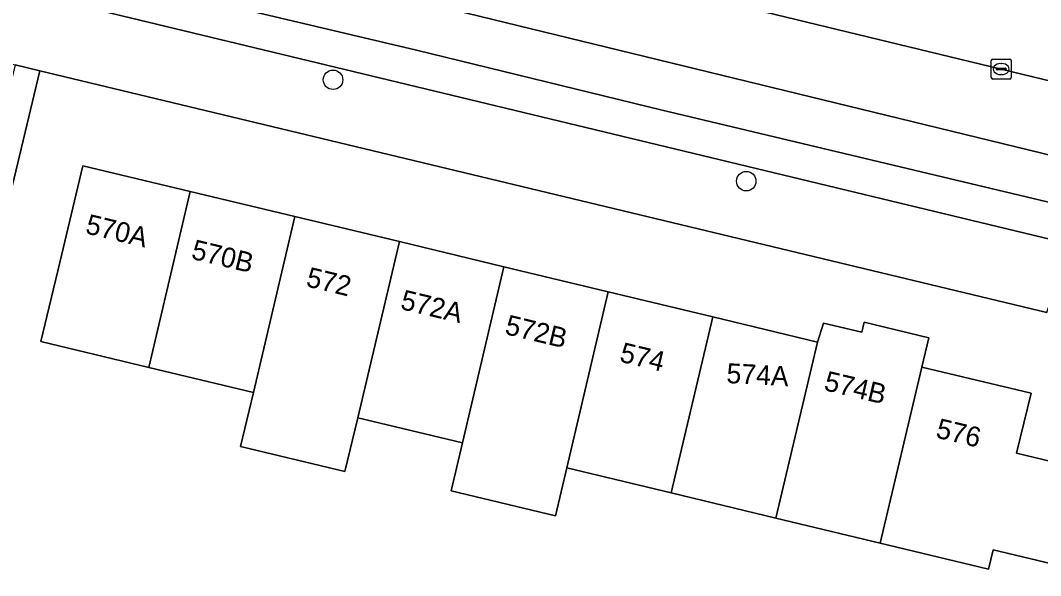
# Model space of a CAD drawing. Extents: x 157767 to 159172, y 387839 to 389425.
# Drawn here: x 158640.4 to 158691.6, y 388114.7 to 388142.5 of the extents above; entities that cross this region are included whole.
import ezdxf

# ---------------------------------------------------------------- set-up
doc = ezdxf.new("R2010")
doc.units = 0
for name, color, linetype in [('IMGEO_Berm_groen', 7, 'Continuous'), ('IMGEO_Boom', 7, 'Continuous'), ('IMGEO_Erf', 7, 'Continuous'), ('IMGEO_Kolk', 7, 'Continuous'), ('IMGEO_Pand', 7, 'Continuous'), ('IMGEO_Pand_nummerreeks', 7, 'Continuous'), ('IMGEO_Parkeervlak_open', 7, 'Continuous'), ('IMGEO_Rijbaan_lokaal_gesloten', 7, 'Continuous'), ('IMGEO_Voetpad_open', 7, 'Continuous')]:
    doc.layers.add(name, color=color, linetype=linetype)

msp = doc.modelspace()

# ---------------------------------------------------------------- linework, layer by layer
at = {"layer": 'IMGEO_Berm_groen'}
msp.add_lwpolyline([(158645.432, 388150.672), (158665.345, 388145.992), (158678.854, 388142.706), (158696.862, 388138.362), (158697.567, 388138.192), (158699.866, 388138.031)], dxfattribs=at)
at = {"layer": 'IMGEO_Boom'}
for centre in [(158656.082, 388139.564), (158676.844, 388134.473)]:
    msp.add_circle(centre, 0.489, dxfattribs=at)
at = {"layer": 'IMGEO_Erf'}
for points in [[(158691.944, 388127.877), (158641.347, 388140.021), (158634.406, 388111.104)], [(158692.191, 388115.259), (158689.254, 388115.963), (158689.02, 388114.99), (158683.578, 388116.296), (158678.326, 388117.556), (158673.076, 388118.816), (158667.824, 388120.077), (158667.254, 388117.661), (158662.014, 388118.918), (158662.583, 388121.335), (158657.331, 388122.595), (158656.681, 388119.885), (158651.429, 388121.145), (158652.079, 388123.855), (158646.829, 388125.115), (158641.397, 388126.419), (158642.35, 388130.39), (158643.517, 388135.251), (158648.905, 388133.958), (158654.157, 388132.697), (158659.412, 388131.436), (158664.663, 388130.176), (158669.91, 388128.917), (158675.167, 388127.655), (158680.418, 388126.395), (158680.729, 388127.349), (158682.645, 388126.893), (158682.763, 388127.388), (158686.016, 388126.605), (158685.668, 388125.135), (158691.151, 388123.819), (158690.43, 388120.815), (158693.356, 388120.112)]]:
    msp.add_lwpolyline(points, dxfattribs=at)
at = {"layer": 'IMGEO_Kolk'}
for p, q in [((158689.155, 388139.676), (158689.155, 388140.528)), ((158689.23, 388140.602), (158690.082, 388140.602)), ((158689.414, 388140.096), (158689.414, 388140.108)), ((158689.457, 388140.145), (158689.855, 388140.145)), ((158689.643, 388140.382), (158689.668, 388140.382)), ((158689.898, 388140.108), (158689.898, 388140.096)), ((158690.156, 388140.528), (158690.156, 388139.676)), ((158690.082, 388139.602), (158689.23, 388139.602)), ((158689.852, 388140.059), (158689.454, 388140.059)), ((158689.666, 388139.822), (158689.641, 388139.822))]:
    msp.add_line(p, q, dxfattribs=at)
for points in [[(158689.155, 388139.676), (158689.155, 388140.528)], [(158689.23, 388140.602), (158690.082, 388140.602)], [(158690.156, 388140.528), (158690.156, 388139.676)], [(158690.082, 388139.602), (158689.23, 388139.602)]]:
    msp.add_lwpolyline(points, dxfattribs=at)
for centre, radius, start, end in [((158689.232, 388140.526), 0.0765, 91.552, 178.448), ((158689.232, 388140.526), 0.0765, 91.552, 178.448), ((158689.454, 388140.105), 0.0403, 85.8775, 175.7526), ((158689.451, 388140.095), 0.0366, 178.938, 274.7102), ((158689.855, 388140.102), 0.043, 264.8664, 352.4533), ((158689.859, 388140.107), 0.0386, 1.7309, 96.639), ((158690.08, 388140.526), 0.0765, 1.552, 88.448), ((158690.08, 388140.526), 0.0765, 1.552, 88.448), ((158689.232, 388139.678), 0.0765, 181.552, 268.448), ((158689.232, 388139.678), 0.0765, 181.552, 268.448), ((158690.08, 388139.678), 0.0765, 271.552, 358.448), ((158690.08, 388139.678), 0.0765, 271.552, 358.448)]:
    msp.add_arc(centre, radius, start, end, dxfattribs=at)
for centre, major_axis, ratio, start_param, end_param in [((158689.642, 388140.102), (-0.387, 0.002), 0.722429, 4.712389, 7.853982), ((158689.667, 388140.102), (-0.39, 0.002), 0.717154, 1.570796, 4.712389)]:
    msp.add_ellipse(centre, major_axis=major_axis, ratio=ratio, start_param=start_param, end_param=end_param, dxfattribs=at)
at = {"layer": 'IMGEO_Pand'}
for points in [[(158646.829, 388125.115), (158648.905, 388133.958), (158643.517, 388135.251), (158642.35, 388130.39), (158641.397, 388126.419)], [(158654.157, 388132.697), (158648.905, 388133.958), (158646.829, 388125.115), (158652.079, 388123.855)], [(158654.157, 388132.697), (158652.079, 388123.855), (158651.429, 388121.145), (158656.681, 388119.885), (158657.331, 388122.595), (158659.412, 388131.436)], [(158664.663, 388130.176), (158659.412, 388131.436), (158657.331, 388122.595), (158662.583, 388121.335)], [(158669.91, 388128.917), (158664.663, 388130.176), (158662.583, 388121.335), (158662.014, 388118.918), (158667.254, 388117.661), (158667.824, 388120.077)], [(158669.91, 388128.917), (158667.824, 388120.077), (158673.076, 388118.816), (158675.167, 388127.655)], [(158678.326, 388117.556), (158680.418, 388126.395), (158675.167, 388127.655), (158673.076, 388118.816)], [(158685.668, 388125.135), (158686.016, 388126.605), (158682.763, 388127.388), (158682.645, 388126.893), (158680.729, 388127.349), (158680.418, 388126.395), (158678.326, 388117.556), (158683.578, 388116.296)], [(158691.151, 388123.819), (158685.668, 388125.135), (158683.578, 388116.296), (158689.02, 388114.99), (158689.254, 388115.963), (158692.191, 388115.259), (158693.356, 388120.112), (158690.43, 388120.815)]]:
    msp.add_lwpolyline(points, close=True, dxfattribs=at)
at = {"layer": 'IMGEO_Parkeervlak_open'}
for points in [[(158696.145, 388132.346), (158694.421, 388132.848), (158672.619, 388138.031), (158660.276, 388141.048), (158643.375, 388145.058)], [(158642.265, 388143.54), (158693.074, 388131.323)]]:
    msp.add_lwpolyline(points, dxfattribs=at)
at = {"layer": 'IMGEO_Rijbaan_lokaal_gesloten'}
for points in [[(158726.373, 388106.161), (158721.077, 388114.643), (158715.254, 388123.838), (158713.652, 388126.449), (158713.046, 388127.438), (158712.568, 388128.281), (158711.679, 388129.084), (158710.125, 388130.777), (158708.377, 388132.377), (158706.878, 388133.633), (158705.213, 388134.72), (158703.592, 388135.668), (158701.693, 388136.525), (158699.357, 388137.377), (158697.567, 388138.192), (158696.862, 388138.362), (158678.854, 388142.706), (158665.345, 388145.992), (158645.432, 388150.672)], [(158696.239, 388134.766), (158682.624, 388138.085), (158662.189, 388143.066), (158642.92, 388147.742)], [(158642.92, 388147.742), (158662.189, 388143.066), (158682.624, 388138.085), (158696.239, 388134.766)], [(158643.375, 388145.058), (158660.276, 388141.048), (158672.619, 388138.031), (158694.421, 388132.848), (158696.145, 388132.346), (158696.262, 388132.312)]]:
    msp.add_lwpolyline(points, dxfattribs=at)
at = {"layer": 'IMGEO_Voetpad_open'}
msp.add_lwpolyline([(158589.589, 388205.583), (158591.997, 388201.731), (158596.931, 388193.835), (158605.271, 388180.491), (158606.085, 388179.189), (158628.661, 388143.066), (158640.111, 388140.318), (158641.347, 388140.021), (158691.944, 388127.877), (158693.074, 388131.323), (158642.265, 388143.54)], dxfattribs=at)
msp.add_lwpolyline([(158639.682, 388102.281), (158634.406, 388111.104), (158641.347, 388140.021), (158640.111, 388140.318), (158638.777, 388134.761), (158637.649, 388129.891), (158636.799, 388126.225), (158633.624, 388112.478), (158633.389, 388112.536), (158633.344, 388112.365), (158629.257, 388113.448), (158629.286, 388113.556), (158618.743, 388116.175), (158620.734, 388113.04), (158621.79, 388113.525), (158632.456, 388111.061), (158637.971, 388101.852), (158639.872, 388098.818), (158643.277, 388093.387), (158645.347, 388090.085), (158646.674, 388090.915), (158646.227, 388091.63), (158643.095, 388096.772)], close=True, dxfattribs=at)

# ---------------------------------------------------------------- texts
at = {"layer": 'IMGEO_Pand_nummerreeks'}
for s, rotation, p in [('570A', 346.5055, (158643.59, 388131.861)), ('570B', 346.4989, (158648.91, 388130.584)), ('572', 346.5063, (158654.677, 388129.2)), ('572A', 346.5067, (158659.417, 388128.062)), ('572B', 346.5068, (158664.667, 388126.803)), ('574', 346.501, (158670.433, 388125.419)), ('574A', 357.0026, (158675.832, 388124.335)), ('574B', 346.6157, (158680.7, 388123.984)), ('576', 346.5068, (158686.323, 388121.605))]:
    msp.add_text(s, height=1, rotation=rotation, dxfattribs=at).set_placement(p)

doc.saveas('drawing.dxf')
